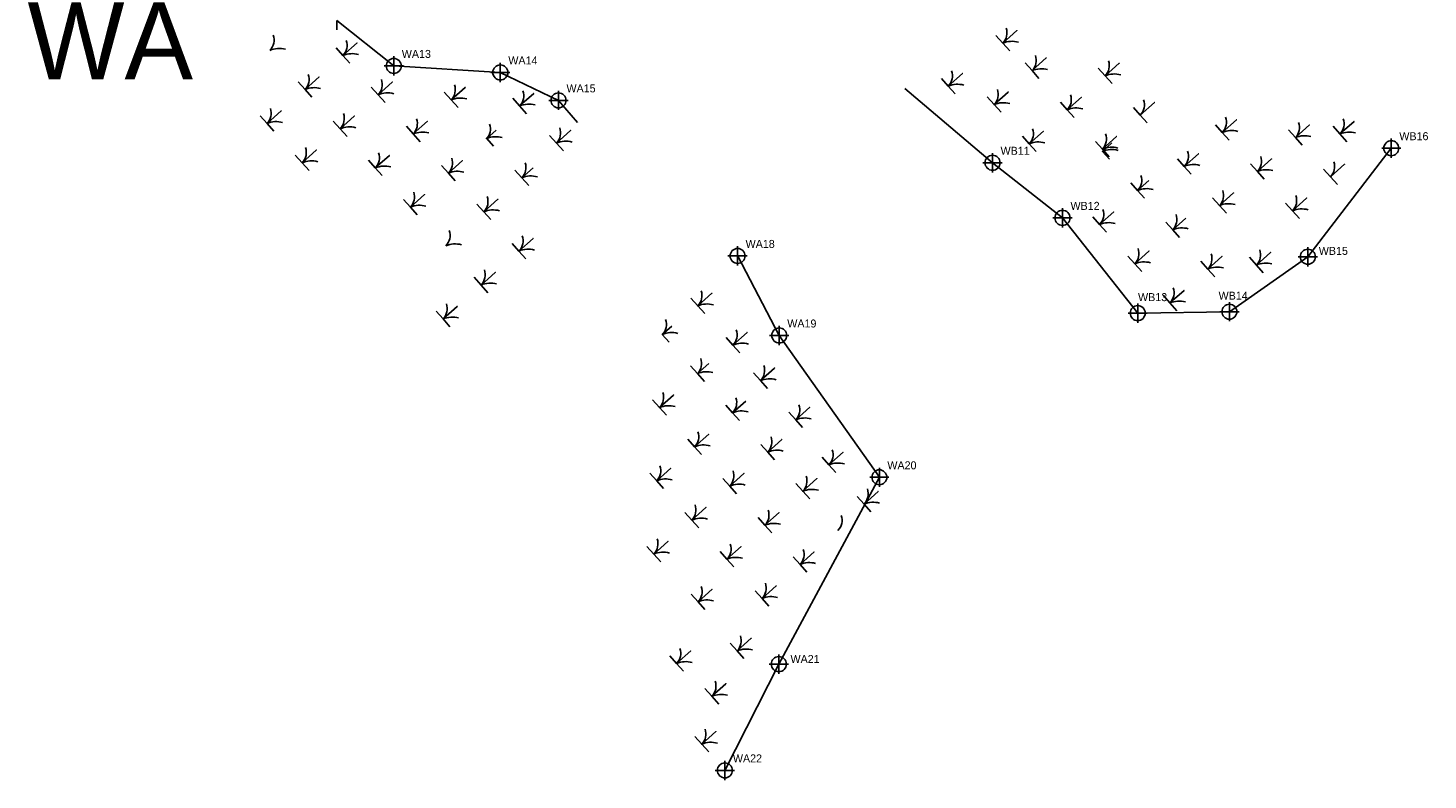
# Model space of a CAD drawing. Extents: x 2126502 to 2127032, y 149550 to 150101.
# Drawn here: x 2126594.6 to 2127032, y 149549.8 to 149784.8 of the extents above; entities that cross this region are included whole.
import ezdxf

# ---------------------------------------------------------------- set-up
doc = ezdxf.new("R2010")
doc.units = 0
for name, color, linetype in [('Default', 7, 'Continuous'), ('Exist Environmental Wetland Boundary', 7, 'Continuous'), ('Exist Environmental Wetland Boundary Cogo Number', 7, 'Continuous'), ('Exist Environmental Wetland Boundary Cogo Point CELL', 7, 'Continuous'), ('Exist Hydro Swamp or Marsh', 7, 'Continuous')]:
    doc.layers.add(name, color=color, linetype=linetype)

msp = doc.modelspace()

# ---------------------------------------------------------------- linework, layer by layer
at = {"layer": 'Exist Environmental Wetland Boundary'}
for p, q in [((2126708.85, 149772.96), (2126691.01, 149787.19)), ((2126742.14, 149770.92), (2126708.85, 149772.96))]:
    msp.add_line(p, q, dxfattribs=at)
for points in [[(2126742.14, 149770.92), (2126760.31, 149762.2), (2126766.23, 149755.28)], [(2126868.57, 149765.91), (2126895.93, 149742.7), (2126917.78, 149725.48), (2126941.29, 149695.71), (2126969.94, 149696.17), (2126994.44, 149713.33), (2127020.52, 149747.25)], [(2126816.3, 149713.52), (2126829.29, 149688.73), (2126860.56, 149644.41), (2126829.15, 149586.03), (2126812.3, 149552.82)]]:
    msp.add_lwpolyline(points, dxfattribs=at)
at = {"layer": 'Exist Environmental Wetland Boundary Cogo Point CELL'}
for points in [[(2126691.01, 149787.19), (2126691.01, 149784.19)], [(2126708.85, 149775.96), (2126708.85, 149772.96)], [(2126705.85, 149772.96), (2126708.85, 149772.96)], [(2126708.85, 149772.96), (2126711.85, 149772.96)], [(2126708.85, 149772.96), (2126708.85, 149769.96)], [(2126742.14, 149773.92), (2126742.14, 149770.92)], [(2126739.14, 149770.92), (2126742.14, 149770.92)], [(2126742.14, 149770.92), (2126745.14, 149770.92)], [(2126742.14, 149770.92), (2126742.14, 149767.92)], [(2126760.31, 149765.2), (2126760.31, 149762.2)], [(2126757.31, 149762.2), (2126760.31, 149762.2)], [(2126760.31, 149762.2), (2126763.31, 149762.2)], [(2126760.31, 149762.2), (2126760.31, 149759.2)], [(2127020.52, 149750.25), (2127020.52, 149747.25)], [(2126895.93, 149745.7), (2126895.93, 149742.7)], [(2127017.52, 149747.25), (2127020.52, 149747.25)], [(2127020.52, 149747.25), (2127023.52, 149747.25)], [(2127020.52, 149747.25), (2127020.52, 149744.25)], [(2126892.93, 149742.7), (2126895.93, 149742.7)], [(2126895.93, 149742.7), (2126898.93, 149742.7)], [(2126895.93, 149742.7), (2126895.93, 149739.7)], [(2126917.78, 149728.48), (2126917.78, 149725.48)], [(2126914.78, 149725.48), (2126917.78, 149725.48)], [(2126917.78, 149725.48), (2126920.78, 149725.48)], [(2126917.78, 149725.48), (2126917.78, 149722.48)], [(2126816.27, 149716.59), (2126816.27, 149713.59)], [(2126994.44, 149716.33), (2126994.44, 149713.33)], [(2126813.27, 149713.59), (2126816.27, 149713.59)], [(2126816.27, 149713.59), (2126819.27, 149713.59)], [(2126816.27, 149713.59), (2126816.27, 149710.59)], [(2126991.44, 149713.33), (2126994.44, 149713.33)], [(2126994.44, 149713.33), (2126997.44, 149713.33)], [(2126994.44, 149713.33), (2126994.44, 149710.33)], [(2126941.29, 149698.71), (2126941.29, 149695.71)], [(2126969.94, 149699.17), (2126969.94, 149696.17)], [(2126938.29, 149695.71), (2126941.29, 149695.71)], [(2126941.29, 149695.71), (2126944.29, 149695.71)], [(2126941.29, 149695.71), (2126941.29, 149692.71)], [(2126966.94, 149696.17), (2126969.94, 149696.17)], [(2126969.94, 149696.17), (2126972.94, 149696.17)], [(2126969.94, 149696.17), (2126969.94, 149693.17)], [(2126826.29, 149688.73), (2126829.29, 149688.73)], [(2126829.29, 149691.73), (2126829.29, 149688.73)], [(2126829.29, 149688.73), (2126832.29, 149688.73)], [(2126829.29, 149688.73), (2126829.29, 149685.73)], [(2126860.56, 149647.41), (2126860.56, 149644.41)], [(2126857.56, 149644.41), (2126860.56, 149644.41)], [(2126860.56, 149644.41), (2126863.56, 149644.41)], [(2126860.56, 149644.41), (2126860.56, 149641.41)], [(2126829.15, 149589.03), (2126829.15, 149586.03)], [(2126826.15, 149586.03), (2126829.15, 149586.03)], [(2126829.15, 149586.03), (2126832.15, 149586.03)], [(2126829.15, 149586.03), (2126829.15, 149583.03)], [(2126812.3, 149555.82), (2126812.3, 149552.82)], [(2126809.3, 149552.82), (2126812.3, 149552.82)], [(2126812.3, 149552.82), (2126815.3, 149552.82)], [(2126812.3, 149552.82), (2126812.3, 149549.82)]]:
    msp.add_lwpolyline(points, dxfattribs=at)
for centre in [(2126708.85, 149772.96), (2126742.14, 149770.92), (2126760.31, 149762.2), (2127020.52, 149747.25), (2126895.93, 149742.7), (2126917.78, 149725.48), (2126816.27, 149713.59), (2126994.44, 149713.33), (2126941.29, 149695.71), (2126969.94, 149696.17), (2126829.29, 149688.73), (2126860.56, 149644.41), (2126829.15, 149586.03), (2126812.3, 149552.82)]:
    msp.add_circle(centre, 2.34, dxfattribs=at)
at = {"layer": 'Exist Hydro Swamp or Marsh'}
for points in [[(2126897, 149782.45), (2126899.15, 149780.05), (2126903.56, 149784), (2126899.15, 149780.05), (2126901.3, 149777.65)], [(2126690.82, 149778.61), (2126692.98, 149776.2), (2126697.38, 149780.15), (2126692.98, 149776.2), (2126695.13, 149773.8)], [(2126906.13, 149773.89), (2126908.28, 149771.49), (2126912.69, 149775.44), (2126908.28, 149771.49), (2126910.44, 149769.08)], [(2126928.96, 149772.26), (2126931.12, 149769.85), (2126935.52, 149773.8), (2126931.12, 149769.85), (2126933.27, 149767.45)], [(2126678.97, 149767.98), (2126681.12, 149765.58), (2126685.53, 149769.53), (2126681.12, 149765.58), (2126683.27, 149763.18)], [(2126701.8, 149766.35), (2126703.95, 149763.95), (2126708.36, 149767.9), (2126703.95, 149763.95), (2126706.11, 149761.55)], [(2126879.95, 149769.05), (2126882.11, 149766.65), (2126886.51, 149770.6), (2126882.11, 149766.65), (2126884.26, 149764.25)], [(2126724.63, 149764.72), (2126726.79, 149762.32), (2126731.19, 149766.27), (2126726.79, 149762.32), (2126728.94, 149759.92)], [(2126746.02, 149762.84), (2126748.18, 149760.44), (2126752.58, 149764.39), (2126748.18, 149760.44), (2126750.33, 149758.04)], [(2126894.27, 149763.27), (2126896.43, 149760.87), (2126900.83, 149764.81), (2126896.43, 149760.87), (2126898.58, 149758.46)], [(2126917.11, 149761.64), (2126919.26, 149759.23), (2126923.67, 149763.18), (2126919.26, 149759.23), (2126921.41, 149756.83)], [(2126667.11, 149757.36), (2126669.26, 149754.96), (2126673.67, 149758.91), (2126669.26, 149754.96), (2126671.42, 149752.56)], [(2126939.94, 149760), (2126942.09, 149757.6), (2126946.5, 149761.55), (2126942.09, 149757.6), (2126944.25, 149755.2)], [(2126689.95, 149755.73), (2126692.1, 149753.33), (2126696.51, 149757.28), (2126692.1, 149753.33), (2126694.25, 149750.93)], [(2126712.78, 149754.1), (2126714.93, 149751.7), (2126719.34, 149755.65), (2126714.93, 149751.7), (2126717.08, 149749.29)], [(2126965.55, 149754.6), (2126967.71, 149752.19), (2126972.11, 149756.14), (2126967.71, 149752.19), (2126969.86, 149749.79)], [(2126988.39, 149752.97), (2126990.54, 149750.56), (2126994.95, 149754.51), (2126990.54, 149750.56), (2126992.69, 149748.16)], [(2127002.32, 149754.1), (2127004.47, 149751.69), (2127008.88, 149755.64), (2127004.47, 149751.69), (2127006.62, 149749.29)], [(2126740.81, 149752.88), (2126737.88, 149750.25), (2126740.03, 149747.85)], [(2126757.53, 149751.25), (2126759.68, 149748.84), (2126764.09, 149752.79), (2126759.68, 149748.84), (2126761.83, 149746.44)], [(2126905.25, 149751.01), (2126907.4, 149748.61), (2126911.81, 149752.56), (2126907.4, 149748.61), (2126909.56, 149746.21)], [(2126928.08, 149749.38), (2126930.24, 149746.98), (2126934.64, 149750.93), (2126930.24, 149746.98), (2126932.39, 149744.58)], [(2126678.09, 149745.11), (2126680.24, 149742.71), (2126684.65, 149746.66), (2126680.24, 149742.71), (2126682.39, 149740.31)], [(2126933.21, 149748.9), (2126930.27, 149746.26), (2126932.42, 149743.86)], [(2126953.7, 149743.98), (2126955.85, 149741.57), (2126960.26, 149745.52), (2126955.85, 149741.57), (2126958, 149739.17)], [(2126700.92, 149743.48), (2126703.07, 149741.08), (2126707.48, 149745.02), (2126703.07, 149741.08), (2126705.23, 149738.67)], [(2126723.76, 149741.85), (2126725.91, 149739.44), (2126730.32, 149743.39), (2126725.91, 149739.44), (2126728.06, 149737.04)], [(2126746.7, 149740.4), (2126748.85, 149738), (2126752.37, 149741.15)], [(2126752.37, 149741.15), (2126748.85, 149738), (2126751, 149735.59)], [(2126976.53, 149742.34), (2126978.68, 149739.94), (2126983.09, 149743.89), (2126978.68, 149739.94), (2126980.84, 149737.54)], [(2126999.37, 149740.71), (2127001.52, 149738.31), (2127005.93, 149742.26), (2127001.52, 149738.31), (2127003.67, 149735.91)], [(2126939.09, 149736.41), (2126941.25, 149734.01), (2126944.77, 149737.16)], [(2126944.77, 149737.16), (2126941.25, 149734.01), (2126943.4, 149731.61)], [(2126711.9, 149731.22), (2126714.05, 149728.82), (2126718.46, 149732.77), (2126714.05, 149728.82), (2126716.2, 149726.42)], [(2126964.68, 149731.72), (2126966.83, 149729.32), (2126971.24, 149733.27), (2126966.83, 149729.32), (2126968.98, 149726.92)], [(2126734.84, 149729.78), (2126737, 149727.37), (2126741.4, 149731.32), (2126737, 149727.37), (2126739.15, 149724.97)], [(2126987.51, 149730.09), (2126989.66, 149727.69), (2126994.07, 149731.64), (2126989.66, 149727.69), (2126991.81, 149725.29)], [(2126927.24, 149725.79), (2126929.39, 149723.39), (2126933.8, 149727.34), (2126929.39, 149723.39), (2126931.54, 149720.99)], [(2126950.07, 149724.16), (2126952.22, 149721.76), (2126956.32, 149725.43)], [(2126956.32, 149725.43), (2126952.22, 149721.76), (2126954.38, 149719.35)], [(2126745.82, 149717.52), (2126747.97, 149715.12), (2126752.38, 149719.07), (2126747.97, 149715.12), (2126750.13, 149712.72)], [(2126938.22, 149713.54), (2126940.37, 149711.13), (2126944.78, 149715.08), (2126940.37, 149711.13), (2126942.52, 149708.73)], [(2126961.05, 149711.9), (2126963.2, 149709.5), (2126967.61, 149713.45), (2126963.2, 149709.5), (2126965.35, 149707.1)], [(2126976.23, 149713.15), (2126978.38, 149710.75), (2126982.79, 149714.7), (2126978.38, 149710.75), (2126980.53, 149708.35)], [(2126733.97, 149706.9), (2126736.12, 149704.5), (2126740.53, 149708.45), (2126736.12, 149704.5), (2126738.27, 149702.1)], [(2126801.69, 149700.37), (2126803.84, 149697.97), (2126808.25, 149701.92), (2126803.84, 149697.97), (2126806, 149695.57)], [(2126949.19, 149701.28), (2126951.35, 149698.88), (2126955.75, 149702.83), (2126951.35, 149698.88), (2126953.5, 149696.48)], [(2126722.11, 149696.28), (2126724.26, 149693.88), (2126728.67, 149697.83), (2126724.26, 149693.88), (2126726.41, 149691.48)], [(2126795.69, 149691.69), (2126792.75, 149689.06), (2126794.9, 149686.65)], [(2126812.67, 149688.12), (2126814.82, 149685.72), (2126819.23, 149689.67), (2126814.82, 149685.72), (2126816.97, 149683.31)], [(2126801.57, 149679.2), (2126803.72, 149676.8), (2126807.24, 149679.95)], [(2126807.24, 149679.95), (2126803.72, 149676.8), (2126805.88, 149674.4)], [(2126821.29, 149677.01), (2126823.44, 149674.61), (2126827.85, 149678.55), (2126823.44, 149674.61), (2126825.59, 149672.2)], [(2126789.71, 149668.58), (2126791.87, 149666.18), (2126796.27, 149670.13), (2126791.87, 149666.18), (2126794.02, 149663.78)], [(2126812.55, 149666.95), (2126814.7, 149664.55), (2126818.8, 149668.22)], [(2126818.8, 149668.22), (2126814.7, 149664.55), (2126816.85, 149662.15)], [(2126832.27, 149664.75), (2126834.42, 149662.35), (2126838.83, 149666.3), (2126834.42, 149662.35), (2126836.57, 149659.95)], [(2126800.69, 149656.33), (2126802.84, 149653.93), (2126807.25, 149657.88), (2126802.84, 149653.93), (2126805, 149651.53)], [(2126823.52, 149654.7), (2126825.68, 149652.3), (2126830.08, 149656.24), (2126825.68, 149652.3), (2126827.83, 149649.89)], [(2126842.65, 149650.69), (2126844.8, 149648.28), (2126849.21, 149652.23), (2126844.8, 149648.28), (2126846.96, 149645.88)], [(2126788.84, 149645.71), (2126790.99, 149643.31), (2126795.4, 149647.26), (2126790.99, 149643.31), (2126793.14, 149640.9)], [(2126811.67, 149644.08), (2126813.82, 149641.67), (2126818.23, 149645.62), (2126813.82, 149641.67), (2126815.97, 149639.27)], [(2126834.5, 149642.44), (2126836.65, 149640.04), (2126841.06, 149643.99), (2126836.65, 149640.04), (2126838.81, 149637.64)], [(2126853.63, 149638.43), (2126855.78, 149636.03), (2126860.19, 149639.98), (2126855.78, 149636.03), (2126857.93, 149633.63)], [(2126799.81, 149633.46), (2126801.97, 149631.05), (2126806.37, 149635), (2126801.97, 149631.05), (2126804.12, 149628.65)], [(2126822.65, 149631.82), (2126824.8, 149629.42), (2126829.21, 149633.37), (2126824.8, 149629.42), (2126826.95, 149627.02)], [(2126787.96, 149622.83), (2126790.11, 149620.43), (2126794.52, 149624.38), (2126790.11, 149620.43), (2126792.26, 149618.03)], [(2126810.79, 149621.2), (2126812.94, 149618.8), (2126817.35, 149622.75), (2126812.94, 149618.8), (2126815.09, 149616.4)], [(2126833.62, 149619.57), (2126835.78, 149617.17), (2126840.18, 149621.12), (2126835.78, 149617.17), (2126837.93, 149614.76)], [(2126821.77, 149608.95), (2126823.92, 149606.55), (2126828.33, 149610.49), (2126823.92, 149606.55), (2126826.07, 149604.14)], [(2126801.76, 149607.9), (2126803.91, 149605.5), (2126808.32, 149609.45), (2126803.91, 149605.5), (2126806.06, 149603.1)], [(2126813.96, 149592.55), (2126816.11, 149590.15), (2126820.52, 149594.1), (2126816.11, 149590.15), (2126818.26, 149587.75)], [(2126795.07, 149588.61), (2126797.22, 149586.21), (2126801.63, 149590.16), (2126797.22, 149586.21), (2126799.37, 149583.81)], [(2126806.08, 149578.38), (2126808.24, 149575.97), (2126812.64, 149579.92), (2126808.24, 149575.97), (2126810.39, 149573.57)], [(2126802.94, 149563.42), (2126805.09, 149561.01), (2126809.5, 149564.96), (2126805.09, 149561.01), (2126807.24, 149558.61)]]:
    msp.add_lwpolyline(points, dxfattribs=at)
for centre, radius, start, end in [((2126895.83, 149783.26), 4.61, 315.9957, 19.3903), ((2126666.83, 149781.04), 4.61, 315.9957, 19.3903), ((2126689.66, 149779.41), 4.61, 315.9957, 19.3903), ((2126902.02, 149773.44), 7.21, 73.9828, 113.4775), ((2126673.01, 149771.22), 7.21, 73.9828, 113.4775), ((2126695.85, 149769.59), 7.21, 73.9828, 113.4775), ((2126904.97, 149774.69), 4.61, 315.9957, 19.3903), ((2126911.15, 149764.87), 7.21, 73.9828, 113.4775), ((2126927.8, 149773.06), 4.61, 315.9957, 19.3903), ((2126677.8, 149768.79), 4.61, 315.9957, 19.3903), ((2126700.64, 149767.15), 4.61, 315.9957, 19.3903), ((2126878.79, 149769.86), 4.61, 315.9957, 19.3903), ((2126884.98, 149760.04), 7.21, 73.9828, 113.4775), ((2126933.99, 149763.24), 7.21, 73.9828, 113.4775), ((2126683.99, 149758.97), 7.21, 73.9828, 113.4775), ((2126706.83, 149757.34), 7.21, 73.9828, 113.4775), ((2126723.47, 149765.52), 4.61, 315.9957, 19.3903), ((2126729.66, 149755.71), 7.21, 73.9828, 113.4775), ((2126744.86, 149763.64), 4.61, 315.9957, 19.3903), ((2126893.11, 149764.07), 4.61, 315.9957, 19.3903), ((2126915.94, 149762.44), 4.61, 315.9957, 19.3903), ((2126665.95, 149758.17), 4.61, 315.9957, 19.3903), ((2126751.05, 149753.83), 7.21, 73.9828, 113.4775), ((2126899.3, 149754.25), 7.21, 73.9828, 113.4775), ((2126922.13, 149752.62), 7.21, 73.9828, 113.4775), ((2126938.78, 149760.8), 4.61, 315.9957, 19.3903), ((2126672.14, 149748.35), 7.21, 73.9828, 113.4775), ((2126688.78, 149756.53), 4.61, 315.9957, 19.3903), ((2126711.61, 149754.9), 4.61, 315.9957, 19.3903), ((2126734.45, 149753.27), 4.61, 315.9957, 19.3903), ((2126964.39, 149755.4), 4.61, 315.9957, 19.3903), ((2126987.22, 149753.77), 4.61, 315.9957, 19.3903), ((2127001.15, 149754.9), 4.61, 315.9957, 19.3903), ((2126694.97, 149746.72), 7.21, 73.9828, 113.4775), ((2126717.8, 149745.08), 7.21, 73.9828, 113.4775), ((2126740.75, 149743.64), 7.21, 73.9828, 113.4775), ((2126756.36, 149752.05), 4.61, 315.9957, 19.3903), ((2126904.09, 149751.82), 4.61, 315.9957, 19.3903), ((2126926.92, 149750.18), 4.61, 315.9957, 19.3903), ((2126970.58, 149745.58), 7.21, 73.9828, 113.4775), ((2126993.41, 149743.95), 7.21, 73.9828, 113.4775), ((2127007.34, 149745.08), 7.21, 73.9828, 113.4775), ((2126676.92, 149745.91), 4.61, 315.9957, 19.3903), ((2126699.76, 149744.28), 4.61, 315.9957, 19.3903), ((2126762.55, 149742.23), 7.21, 73.9828, 113.4775), ((2126910.28, 149742), 7.21, 73.9828, 113.4775), ((2126933.11, 149740.37), 7.21, 73.9828, 113.4775), ((2126933.14, 149739.65), 7.21, 73.9828, 113.4775), ((2126952.53, 149744.78), 4.61, 315.9957, 19.3903), ((2126683.11, 149736.1), 7.21, 73.9828, 113.4775), ((2126705.95, 149734.46), 7.21, 73.9828, 113.4775), ((2126722.59, 149742.65), 4.61, 315.9957, 19.3903), ((2126745.54, 149741.2), 4.61, 315.9957, 19.3903), ((2126958.72, 149734.96), 7.21, 73.9828, 113.4775), ((2126975.37, 149743.15), 4.61, 315.9957, 19.3903), ((2126998.2, 149741.51), 4.61, 315.9957, 19.3903), ((2126728.78, 149732.83), 7.21, 73.9828, 113.4775), ((2126751.72, 149731.38), 7.21, 73.9828, 113.4775), ((2126937.93, 149737.21), 4.61, 315.9957, 19.3903), ((2126981.56, 149733.33), 7.21, 73.9828, 113.4775), ((2126710.73, 149732.03), 4.61, 315.9957, 19.3903), ((2126944.12, 149727.4), 7.21, 73.9828, 113.4775), ((2126963.51, 149732.52), 4.61, 315.9957, 19.3903), ((2126986.34, 149730.89), 4.61, 315.9957, 19.3903), ((2126716.92, 149722.21), 7.21, 73.9828, 113.4775), ((2126733.68, 149730.58), 4.61, 315.9957, 19.3903), ((2126739.87, 149720.76), 7.21, 73.9828, 113.4775), ((2126926.07, 149726.59), 4.61, 315.9957, 19.3903), ((2126969.7, 149722.71), 7.21, 73.9828, 113.4775), ((2126992.53, 149721.08), 7.21, 73.9828, 113.4775), ((2126932.26, 149716.78), 7.21, 73.9828, 113.4775), ((2126948.91, 149724.96), 4.61, 315.9957, 19.3903), ((2126721.82, 149719.96), 4.61, 315.9957, 19.3903), ((2126744.66, 149718.32), 4.61, 315.9957, 19.3903), ((2126955.1, 149715.14), 7.21, 73.9828, 113.4775), ((2126728.01, 149710.14), 7.21, 73.9828, 113.4775), ((2126750.85, 149708.51), 7.21, 73.9828, 113.4775), ((2126937.05, 149714.34), 4.61, 315.9957, 19.3903), ((2126975.07, 149713.95), 4.61, 315.9957, 19.3903), ((2126943.24, 149704.52), 7.21, 73.9828, 113.4775), ((2126959.88, 149712.71), 4.61, 315.9957, 19.3903), ((2126981.25, 149704.14), 7.21, 73.9828, 113.4775), ((2126732.8, 149707.7), 4.61, 315.9957, 19.3903), ((2126966.07, 149702.89), 7.21, 73.9828, 113.4775), ((2126738.99, 149697.89), 7.21, 73.9828, 113.4775), ((2126800.53, 149701.17), 4.61, 315.9957, 19.3903), ((2126948.03, 149702.09), 4.61, 315.9957, 19.3903), ((2126720.94, 149697.08), 4.61, 315.9957, 19.3903), ((2126806.72, 149691.36), 7.21, 73.9828, 113.4775), ((2126954.22, 149692.27), 7.21, 73.9828, 113.4775), ((2126727.13, 149687.27), 7.21, 73.9828, 113.4775), ((2126789.44, 149692.19), 4.61, 315.9957, 19.3903), ((2126795.62, 149682.44), 7.21, 73.9828, 113.4775), ((2126811.5, 149688.92), 4.61, 315.9957, 19.3903), ((2126817.69, 149679.11), 7.21, 73.9828, 113.4775), ((2126800.41, 149680.01), 4.61, 315.9957, 19.3903), ((2126806.59, 149670.19), 7.21, 73.9828, 113.4775), ((2126820.12, 149677.81), 4.61, 315.9957, 19.3903), ((2126826.31, 149667.99), 7.21, 73.9828, 113.4775), ((2126788.55, 149669.38), 4.61, 315.9957, 19.3903), ((2126794.74, 149659.57), 7.21, 73.9828, 113.4775), ((2126811.38, 149667.75), 4.61, 315.9957, 19.3903), ((2126831.1, 149665.56), 4.61, 315.9957, 19.3903), ((2126817.57, 149657.94), 7.21, 73.9828, 113.4775), ((2126837.29, 149655.74), 7.21, 73.9828, 113.4775), ((2126799.53, 149657.13), 4.61, 315.9957, 19.3903), ((2126805.72, 149647.32), 7.21, 73.9828, 113.4775), ((2126822.36, 149655.5), 4.61, 315.9957, 19.3903), ((2126828.55, 149645.68), 7.21, 73.9828, 113.4775), ((2126841.49, 149651.49), 4.61, 315.9957, 19.3903), ((2126787.67, 149646.51), 4.61, 315.9957, 19.3903), ((2126810.5, 149644.88), 4.61, 315.9957, 19.3903), ((2126833.34, 149643.25), 4.61, 315.9957, 19.3903), ((2126847.68, 149641.67), 7.21, 73.9828, 113.4775), ((2126793.86, 149636.69), 7.21, 73.9828, 113.4775), ((2126816.69, 149635.06), 7.21, 73.9828, 113.4775), ((2126839.53, 149633.43), 7.21, 73.9828, 113.4775), ((2126852.46, 149639.23), 4.61, 315.9957, 19.3903), ((2126858.65, 149629.42), 7.21, 73.9828, 113.4775), ((2126798.65, 149634.26), 4.61, 315.9957, 19.3903), ((2126804.84, 149624.44), 7.21, 73.9828, 113.4775), ((2126821.48, 149632.62), 4.61, 315.9957, 19.3903), ((2126844.31, 149630.99), 4.61, 315.9957, 19.3903), ((2126827.67, 149622.81), 7.21, 73.9828, 113.4775), ((2126786.79, 149623.64), 4.61, 315.9957, 19.3903), ((2126809.62, 149622), 4.61, 315.9957, 19.3903), ((2126792.98, 149613.82), 7.21, 73.9828, 113.4775), ((2126815.81, 149612.19), 7.21, 73.9828, 113.4775), ((2126832.46, 149620.37), 4.61, 315.9957, 19.3903), ((2126838.65, 149610.56), 7.21, 73.9828, 113.4775), ((2126800.59, 149608.71), 4.61, 315.9957, 19.3903), ((2126820.6, 149609.75), 4.61, 315.9957, 19.3903), ((2126806.78, 149598.89), 7.21, 73.9828, 113.4775), ((2126826.79, 149599.93), 7.21, 73.9828, 113.4775), ((2126812.79, 149593.35), 4.61, 315.9957, 19.3903), ((2126793.9, 149589.41), 4.61, 315.9957, 19.3903), ((2126818.98, 149583.54), 7.21, 73.9828, 113.4775), ((2126800.09, 149579.6), 7.21, 73.9828, 113.4775), ((2126804.92, 149579.18), 4.61, 315.9957, 19.3903), ((2126811.11, 149569.36), 7.21, 73.9828, 113.4775), ((2126801.77, 149564.22), 4.61, 315.9957, 19.3903), ((2126807.96, 149554.4), 7.21, 73.9828, 113.4775)]:
    msp.add_arc(centre, radius, start, end, dxfattribs=at)

# ---------------------------------------------------------------- texts
at = {"layer": 'Default'}
msp.add_text('WA', height=24, dxfattribs=at).set_placement((2126594.42, 149768.79))
at = {"layer": 'Exist Environmental Wetland Boundary Cogo Number'}
for s, p in [('WA13', (2126711.35, 149775.46)), ('WA14', (2126744.64, 149773.42)), ('WA15', (2126762.81, 149764.7)), ('WB16', (2127023.02, 149749.75)), ('WB11', (2126898.43, 149745.2)), ('WB12', (2126920.28, 149727.98)), ('WA18', (2126818.77, 149716.09)), ('WB15', (2126997.86, 149713.92)), ('WB13', (2126941.39, 149699.46)), ('WB14', (2126966.55, 149699.92)), ('WA19', (2126831.79, 149691.23)), ('WA20', (2126863.06, 149646.91)), ('WA21', (2126832.8, 149586.38)), ('WA22', (2126814.8, 149555.32))]:
    msp.add_text(s, height=2.5, dxfattribs=at).set_placement(p)

doc.saveas('drawing.dxf')
